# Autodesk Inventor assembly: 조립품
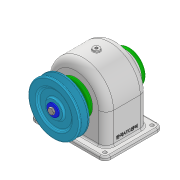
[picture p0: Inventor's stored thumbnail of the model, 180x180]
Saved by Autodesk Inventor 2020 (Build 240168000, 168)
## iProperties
Created: 2022-09
Part Number: 조립품
Document SubType Name: Assembly
Designer: Administrator
Author: Administrator
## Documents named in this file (16)
- C:\Users\Administrator\Desktop\720906V1020\조립품.iam
- C:\Users\Administrator\Desktop\720906V1020\본체.ipt
- C:\Users\Administrator\Desktop\720906V1020\V-벨트풀리.ipt
- C:\Users\Administrator\Desktop\720906V1020\뒤커버.ipt
- C:\Users\Administrator\Desktop\720906V1020\멈춤나사 M4 x 10.ipt
- C:\Users\Administrator\Desktop\720906V1020\베어링 6203.ipt
- C:\Users\Administrator\Desktop\720906V1020\볼트 M3 x 10.ipt
- C:\Users\Administrator\Desktop\720906V1020\스퍼기어.ipt
- C:\Users\Administrator\Desktop\720906V1020\앞커버.ipt
- C:\Users\Administrator\Desktop\720906V1020\오일 실 17 x 30 x 8.ipt
- C:\Users\Administrator\Desktop\720906V1020\와셔 6 x 22.ipt
- C:\Users\Administrator\Desktop\720906V1020\육각머리볼트 M3 x 8.ipt
- C:\Users\Administrator\Desktop\720906V1020\축.ipt
- C:\Users\Administrator\Desktop\720906V1020\칼라.ipt
- C:\Users\Administrator\Desktop\720906V1020\키 5 x 5 x 18.ipt
- C:\Users\Administrator\Desktop\720906V1020\키 6 x 6 x 22.ipt
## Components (5 placed, 2 different names)
1. V-벨트풀리:1 — 플러쉬:2, 플러쉬:3, 각도:1
2. ISO 4762 M3 x 10:1
3. ISO 4762 M3 x 10:2
4. ISO 4762 M3 x 10:3
5. ISO 4762 M3 x 10:4
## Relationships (3: Flush 2, Angle 1)
- 플러쉬:2 [Flush]: V-벨트풀리:1
- 플러쉬:3 [Flush]: V-벨트풀리:1
- 각도:1 [Angle]: V-벨트풀리:1
